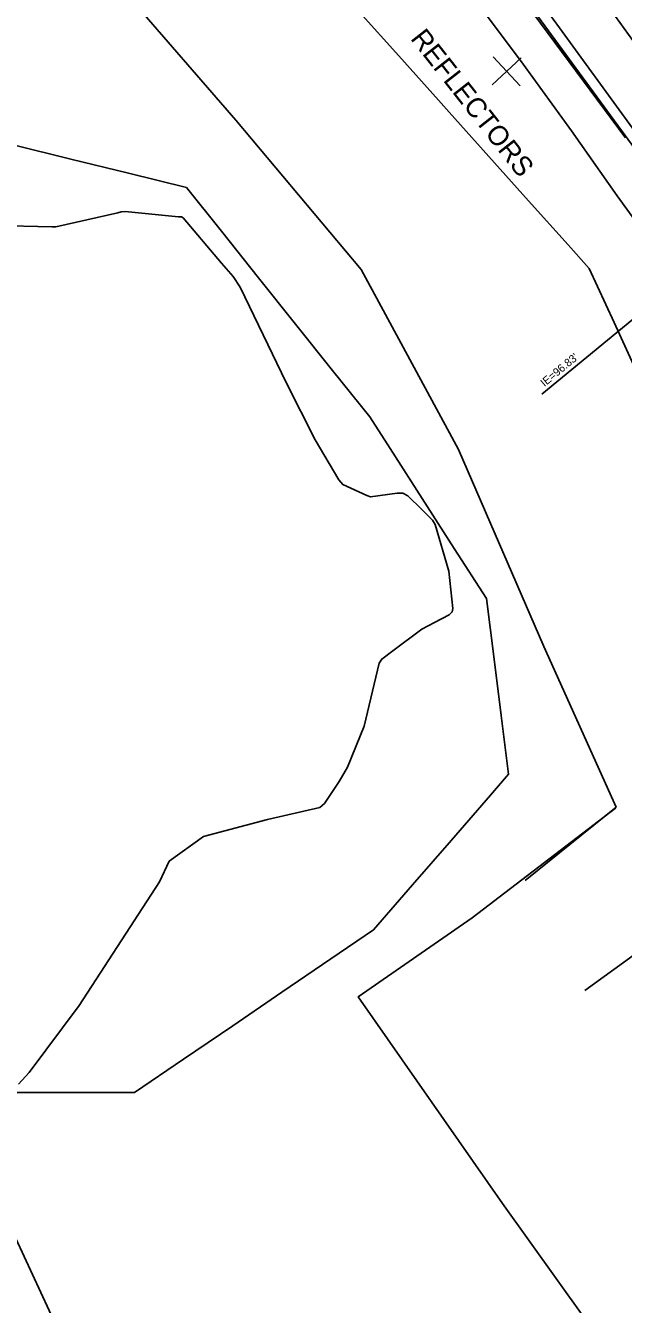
# Model space of a CAD drawing. Extents: x 2132221 to 2141942, y 535736 to 547298.
# Drawn here: x 2136623.7 to 2136774.5, y 541827.9 to 542151 of the extents above; entities that cross this region are included whole.
import ezdxf

# ---------------------------------------------------------------- set-up
doc = ezdxf.new("R2010")
doc.units = 0
for name, color, linetype in [('RD_EX_DR_Inlet_txCode', 7, 'Continuous'), ('RD_EX_DR_Pipe', 7, 'Continuous'), ('RD_EX_Fence_Other', 7, 'Continuous'), ('RD_EX_H2O', 7, 'Continuous'), ('RD_EX_Misc', 7, 'Continuous'), ('RD_EX_Misc_txCode', 7, 'Continuous'), ('RD_EX_Road', 7, 'Continuous'), ('RD_EX_VEG', 7, 'Continuous'), ('RD_HC_Cl', 7, 'Continuous'), ('RD_HC_Data', 7, 'Continuous'), ('TOPO_E_TLIML-Line', 7, 'Continuous')]:
    doc.layers.add(name, color=color, linetype=linetype)

msp = doc.modelspace()

# ---------------------------------------------------------------- linework, layer by layer
at = {"layer": 'RD_EX_DR_Pipe'}
msp.add_line((2136877.85, 542160.1), (2136753.98, 542057.84), dxfattribs=at)
at = {"layer": 'RD_EX_Fence_Other'}
msp.add_line((2136639.78, 542169.81), (2136676.71, 542127.08), dxfattribs=at)
for points in [[(2136732.93, 542043.92), (2136708.38, 542089.37), (2136676.71, 542127.08)], [(2136732.93, 542043.92), (2136754.42, 541994.18), (2136772.69, 541953.59), (2136749.77, 541934.99)], [(2136772.57, 541953.26), (2136736.35, 541925.6), (2136707.57, 541905.61), (2136743.98, 541853.42), (2136785.46, 541795.46), (2136812.04, 541756.88), (2136848.3, 541695.84)]]:
    msp.add_lwpolyline(points, dxfattribs=at)
at = {"layer": 'RD_EX_H2O'}
msp.add_lwpolyline([(2136621.87, 541883.56), (2136624.59, 541886.55), (2136637.18, 541903.42), (2136657.43, 541934.66), (2136659.87, 541939.9), (2136668.52, 541946.11), (2136684.69, 541950.4), (2136697.89, 541953.43), (2136699.07, 541954.48), (2136702.81, 541960.05), (2136704.89, 541963.7), (2136709.13, 541974), (2136712.91, 541989.91), (2136713.57, 541990.94), (2136716.33, 541993.08), (2136723.65, 541998.5), (2136726.88, 542000.19), (2136730.57, 542002.13), (2136731.35, 542002.88), (2136731.52, 542003.75), (2136730.48, 542013.16), (2136726.99, 542024.97), (2136726.35, 542026.04), (2136723.62, 542028.76), (2136720.14, 542032.21), (2136718.83, 542032.91), (2136717.47, 542032.86), (2136710.67, 542031.97), (2136709.76, 542032.31), (2136703.68, 542035.03), (2136702.7, 542036.24), (2136696.71, 542046.31), (2136689.39, 542060.86), (2136677.78, 542084.92), (2136676.04, 542087.64), (2136673.1, 542090.95), (2136663.39, 542102.42), (2136662.98, 542102.68), (2136662.29, 542102.68), (2136648.77, 542104), (2136647.77, 542103.95), (2136646.92, 542103.72), (2136631.29, 542100.14), (2136630.24, 542100.16), (2136626.76, 542100.25), (2136612.37, 542100.61)], dxfattribs=at)
at = {"layer": 'RD_EX_Misc'}
for p, q in [((2136741.44, 542136), (2136748.74, 542142.84)), ((2136741.67, 542143.06), (2136748.51, 542135.77))]:
    msp.add_line(p, q, dxfattribs=at)
for points in [[(2136748.27, 542158.8), (2136757.19, 542146.73), (2136766.1, 542134.67), (2136775.02, 542122.61)], [(2136771.42, 542154.83), (2136780.22, 542142.69)]]:
    msp.add_lwpolyline(points, dxfattribs=at)
at = {"layer": 'RD_EX_Road'}
msp.add_lwpolyline([(2136731.92, 542164.44), (2136749.24, 542141.25), (2136761.39, 542124.37), (2136772.98, 542107.94), (2136817.68, 542046.25), (2136836.63, 542020.92), (2136848.69, 542004.14), (2136863.99, 541983.47), (2136874.17, 541969.26), (2136883.64, 541955.45), (2136892.86, 541941.87), (2136899.54, 541931.26), (2136907.49, 541919.04), (2136928.56, 541886.45), (2136941.62, 541864.12), (2136952.38, 541845.99), (2136964.91, 541823.72), (2136975.48, 541802.86), (2136982.82, 541787.06), (2136987.09, 541779.04), (2136997.47, 541760.32), (2137005.58, 541741.81), (2137017.75, 541714.1), (2137026.6, 541693.64)], dxfattribs=at)
at = {"layer": 'RD_EX_VEG'}
for points in [[(2136707.87, 542154.5), (2136717.87, 542143.31), (2136727.87, 542132.13), (2136730.57, 542129.11), (2136740.57, 542117.93), (2136750.57, 542106.75), (2136760.57, 542095.57), (2136765.91, 542089.6), (2136772.16, 542075.97), (2136778.41, 542062.33)], [(2136619.06, 541881.44), (2136634.06, 541881.44), (2136649.06, 541881.44), (2136651.15, 541881.44), (2136663.54, 541889.89), (2136675.92, 541898.35), (2136688.31, 541906.8), (2136700.7, 541915.26), (2136711.44, 541922.59), (2136721.28, 541933.91), (2136731.12, 541945.24), (2136740.95, 541956.56), (2136745.56, 541961.87), (2136743.68, 541976.75), (2136741.81, 541991.63), (2136739.95, 542006.3), (2136731.85, 542018.92), (2136723.74, 542031.53), (2136715.63, 542044.15), (2136710.51, 542052.12), (2136701.15, 542063.85), (2136691.79, 542075.57), (2136682.44, 542087.3), (2136673.08, 542099.02), (2136664.23, 542110.11), (2136649.67, 542113.7), (2136635.1, 542117.28), (2136620.54, 542120.87)]]:
    msp.add_lwpolyline(points, dxfattribs=at)
at = {"layer": 'RD_HC_Cl'}
for p, q in [((2136543.98, 542440.37), (2136874.2, 541986.92)), ((2136548.76, 542438.96), (2136910.69, 541940.92))]:
    msp.add_line(p, q, dxfattribs=at)
msp.add_arc((2118950.8, 527389.88), 23225.51, 39.112741, 42.881786, dxfattribs=at)
at = {"layer": 'RD_HC_Data'}
msp.add_line((2136874.2, 541986.92), (2136764.83, 541907.27), dxfattribs=at)
msp.add_line((2136874.2, 541986.92), (2136764.83, 541907.27), dxfattribs=at)
at = {"layer": 'TOPO_E_TLIML-Line'}
msp.add_lwpolyline([(2136621.17, 541844.56), (2136627.49, 541830.95), (2136633.8, 541817.35), (2136640.11, 541803.74), (2136646.43, 541790.13), (2136647.94, 541786.86), (2136651.18, 541772.22), (2136654.41, 541757.57), (2136657.64, 541742.92), (2136660.87, 541728.27), (2136664.1, 541713.62), (2136667.33, 541698.98), (2136670.56, 541684.33), (2136673.8, 541669.68), (2136677.03, 541655.03), (2136680.26, 541640.39)], dxfattribs=at)

# ---------------------------------------------------------------- texts
at = {"layer": 'RD_EX_DR_Inlet_txCode'}
msp.add_text("IE=96.83'", height=2, rotation=39.541, dxfattribs=at).set_placement((2136754.61, 542059.66))
at = {"layer": 'RD_EX_Misc_txCode'}
msp.add_text('REFLECTORS', height=5, rotation=308.1519, dxfattribs=at).set_placement((2136720.61, 542147.65))

doc.saveas('drawing.dxf')
